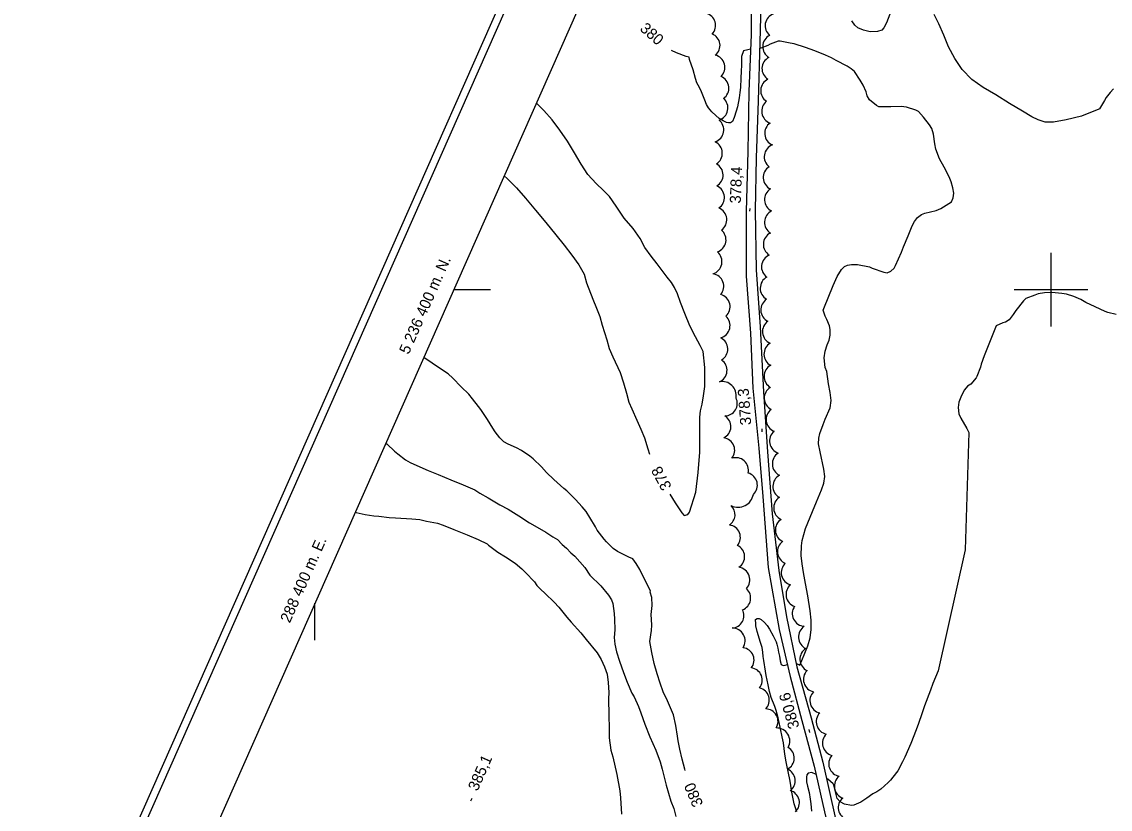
# Model space of a CAD drawing. Extents: x 287698 to 290158, y 5234163 to 5237182.
# Drawn here: x 288320.4 to 288616.1, y 5236258.8 to 5236472.8 of the extents above; entities that cross this region are included whole.
import ezdxf

# ---------------------------------------------------------------- set-up
doc = ezdxf.new("R2010")
doc.units = 0
for name, color, linetype in [('Niveau 1', 7, 'Continuous'), ('Niveau 19', 7, 'Continuous'), ('Niveau 2', 7, 'Continuous'), ('Niveau 3', 7, 'Continuous'), ('Niveau 44', 7, 'Continuous'), ('Niveau 60', 7, 'Continuous'), ('Niveau 61', 7, 'Continuous')]:
    doc.layers.add(name, color=color, linetype=linetype)

msp = doc.modelspace()

# ---------------------------------------------------------------- linework, layer by layer
at = {"layer": 'Niveau 1'}
for points in [[(288540.03, 5236387.65), (288540.05, 5236389.18), (288539.87, 5236390.12), (288539.15, 5236391.91), (288538.65, 5236392.8), (288538.1, 5236394.44), (288538.43, 5236395.32), (288539.48, 5236397.8), (288540.83, 5236401.12), (288541.96, 5236403.55), (288543.09, 5236405.45), (288543.9, 5236406.25), (288544.68, 5236406.67), (288545.84, 5236406.84), (288547.45, 5236406.78), (288550.71, 5236406.15), (288551.43, 5236405.85), (288554.58, 5236404.72), (288555.54, 5236404.55), (288556.47, 5236404.98), (288557.38, 5236405.86), (288557.73, 5236406.58), (288559.39, 5236410.13), (288559.98, 5236411.58), (288561.21, 5236414.61), (288562.31, 5236417.29), (288562.93, 5236418.48), (288563.75, 5236419.56), (288564.8, 5236420.4), (288565.71, 5236420.73), (288568.8, 5236421.49), (288570.09, 5236422.05), (288573, 5236423.83), (288573.44, 5236424.93), (288573.59, 5236426.16), (288573.37, 5236427.65), (288572.93, 5236429.24), (288572.36, 5236430.66), (288570.97, 5236433.29), (288569.76, 5236435.51), (288568.75, 5236438.13), (288568.49, 5236439.61), (288568.07, 5236442.26), (288567.68, 5236443.73), (288567, 5236444.81), (288565.41, 5236446.87), (288564.05, 5236448.38), (288563.27, 5236448.76), (288560.78, 5236449.56), (288559.27, 5236449.73), (288556.5, 5236449.67), (288553.27, 5236449.68), (288552.56, 5236449.98), (288550.72, 5236451.59), (288550.09, 5236452.62), (288549.76, 5236453.72), (288549, 5236455.53), (288548.12, 5236456.91), (288546.64, 5236459.22), (288545.76, 5236459.99), (288544.61, 5236460.69), (288541.62, 5236462.23), (288540.38, 5236462.96), (288538.75, 5236463.67), (288535.82, 5236464.86), (288533.33, 5236465.81), (288530.26, 5236466.78), (288529.17, 5236466.94), (288526.39, 5236467.5), (288525.87, 5236467.49), (288523.72, 5236466.7), (288523.12, 5236466.31), (288521.18, 5236465.57), (288520.88, 5236465.56)], [(288501.66, 5236463.11), (288500.88, 5236463.37), (288498.26, 5236464.34), (288496.92, 5236464.98)], [(288516.45, 5236464.84), (288515.89, 5236463.36), (288515.88, 5236462.83), (288515.92, 5236460.98), (288515.87, 5236459.33), (288515.76, 5236457.45), (288515.64, 5236454.89), (288515.49, 5236453.53), (288515.27, 5236452.14), (288514.84, 5236449.69), (288514.49, 5236448.44), (288513.91, 5236446.72), (288513.44, 5236445.65), (288512.93, 5236445.31), (288512.39, 5236445.29), (288511.85, 5236445.44), (288510.9, 5236445.87), (288509.88, 5236446.5), (288508.99, 5236447.32), (288507.85, 5236448.26), (288506.95, 5236449.36), (288506.42, 5236450.33), (288505.94, 5236451.45), (288505.03, 5236453.71), (288504.47, 5236454.93), (288503.78, 5236456.18), (288503.45, 5236457.37), (288502.76, 5236459.72), (288501.82, 5236462.54), (288501.66, 5236463.11), (288501.66, 5236463.11)], [(288518.36, 5236465.34), (288517.67, 5236465.11), (288516.45, 5236464.84)], [(288617.72, 5236393.25), (288615.44, 5236393.79), (288614.78, 5236394.07), (288611.99, 5236395.31), (288609.47, 5236396.5), (288608.12, 5236397.27), (288606.21, 5236398.09), (288604.21, 5236398.75), (288602.97, 5236398.92), (288600.22, 5236399.18), (288598.29, 5236399.14), (288596.53, 5236398.87), (288595.62, 5236398.51), (288593.21, 5236397.55), (288592.55, 5236396.94), (288590.49, 5236394.33), (288589.78, 5236393.22), (288588.62, 5236391.8), (288587.64, 5236391.11), (288586.95, 5236390.94), (288585.12, 5236390.12), (288584.75, 5236389.24), (288583.27, 5236385.62), (288581.84, 5236382.04), (288581.05, 5236379.78), (288580.88, 5236378.91), (288579.87, 5236376.35), (288579.65, 5236376.06), (288578.21, 5236374.27), (288577.35, 5236373.72), (288576.48, 5236372.78), (288575.71, 5236371.2), (288575.01, 5236369.4), (288574.78, 5236367.99), (288574.98, 5236366.28), (288575.56, 5236365.05), (288577.18, 5236362.27), (288577.7, 5236361.19), (288576.66, 5236329.28)], [(288531.76, 5236297.95), (288532.33, 5236299.21), (288533.97, 5236303.24), (288534.58, 5236305.42), (288534.86, 5236307.65), (288534.85, 5236310.15), (288534.56, 5236312.73), (288533.97, 5236316.75), (288533.3, 5236320.14), (288532.73, 5236323.12), (288532.39, 5236325.51), (288532.16, 5236327.77), (288532.22, 5236330.41), (288532.39, 5236331.85), (288533.32, 5236335.06), (288533.96, 5236336.62), (288535.22, 5236339.71), (288536.28, 5236342.3), (288537.65, 5236345.58), (288538.29, 5236347.37), (288538.56, 5236349.21), (288538.26, 5236351.23), (288537.26, 5236355.96), (288536.88, 5236358.1), (288536.93, 5236359.62), (288537.19, 5236360.86), (288538.08, 5236363.38), (288538.69, 5236364.79), (288539.99, 5236367.88), (288540.31, 5236369.83), (288540.03, 5236372.06), (288539.6, 5236374.44), (288539.08, 5236377.73), (288538.69, 5236378.81), (288538.39, 5236381.44), (288538.67, 5236383.27), (288539.17, 5236384.99), (288539.71, 5236386.3), (288540.03, 5236387.65)], [(288491.2, 5236318.11), (288489.51, 5236321.53), (288488.28, 5236323.99), (288487.33, 5236325.59), (288486.36, 5236326.81), (288485.35, 5236327.32), (288482.21, 5236328.8), (288481.05, 5236329.66), (288479.21, 5236331.47), (288478.64, 5236332.21), (288476.72, 5236334.67), (288476.24, 5236335.51), (288474.73, 5236338.08), (288473.69, 5236339.68), (288472.64, 5236341.02), (288470.82, 5236343.01), (288468.48, 5236345.34), (288467.61, 5236345.99), (288464.9, 5236348.4), (288462.9, 5236350.35), (288461.58, 5236351.81), (288459.34, 5236354.01), (288458.43, 5236354.76), (288456.14, 5236356.28), (288454.82, 5236356.98), (288452.54, 5236357.98), (288451.31, 5236358.67), (288450.27, 5236359.74), (288449.01, 5236361.34), (288448.39, 5236362.33), (288446.89, 5236364.67), (288445.1, 5236367.4), (288444.44, 5236368.24), (288442.86, 5236370.33), (288441.79, 5236371.57), (288439.78, 5236373.61), (288437.52, 5236375.98), (288436.24, 5236377.07), (288434.44, 5236378.32), (288431.86, 5236379.99), (288429.58, 5236381.57)], [(288576.66, 5236329.28), (288569.32, 5236296.38)], [(288500.61, 5236269.3), (288500.49, 5236269.74), (288499.79, 5236272.42), (288499.13, 5236275.09), (288498.67, 5236277.42), (288498.55, 5236278.63), (288498.05, 5236281.55), (288497.41, 5236284.47), (288496.94, 5236285.72), (288495.82, 5236288.26), (288494.67, 5236290.75), (288493.8, 5236293.02), (288492.97, 5236295.61), (288492.17, 5236298.4), (288491.54, 5236301.41), (288491.04, 5236304.43), (288491.5, 5236307.38), (288491.6, 5236308.84), (288491.44, 5236310.4), (288491.42, 5236311.71), (288491.63, 5236314.21), (288491.59, 5236316.31), (288491.1, 5236317.83), (288491.2, 5236318.11)], [(288530.93, 5236258.13), (288530.27, 5236260.25), (288529.95, 5236261.62), (288529.6, 5236263.44), (288529.12, 5236266.42), (288528.61, 5236269.05), (288528.29, 5236270.3), (288528.04, 5236271.73), (288527.74, 5236273.76), (288527.31, 5236276.82), (288527.01, 5236278.52), (288526.52, 5236280.65), (288525.87, 5236283.69), (288525.38, 5236285.65), (288524.95, 5236286.74), (288524.01, 5236289.18), (288523.56, 5236290.82), (288523.17, 5236292.62), (288522.6, 5236295.19), (288522.45, 5236296.32), (288521.99, 5236299.26), (288521.83, 5236300.32), (288521.74, 5236301.47), (288521.53, 5236302.73), (288521.08, 5236304.11), (288520.14, 5236307.09), (288519.86, 5236308.62), (288519.8, 5236309.18), (288519.75, 5236310.35), (288520.19, 5236310.66), (288520.74, 5236310.59), (288521.26, 5236310.33), (288522.2, 5236309.56), (288522.87, 5236308.74), (288523.5, 5236307.72), (288524.56, 5236305.91), (288525.33, 5236304.29), (288525.48, 5236303.67), (288525.83, 5236302.6), (288526, 5236301.52), (288526.26, 5236300.38), (288526.44, 5236299.17), (288526.74, 5236298.16), (288527.21, 5236297.86), (288527.79, 5236297.92), (288528.38, 5236298.15)], [(288530.79, 5236298.37), (288531.47, 5236298.12), (288531.76, 5236297.95)], [(288569.32, 5236296.38), (288567.91, 5236292.95), (288567.27, 5236291.13), (288565.67, 5236286.92), (288564.91, 5236284.73), (288564.05, 5236282.1), (288563.38, 5236280.39), (288561.89, 5236276.67), (288560.3, 5236272.94), (288559.63, 5236271.67), (288558.37, 5236269.21), (288558.01, 5236268.75), (288556.4, 5236266.69), (288555.76, 5236266.08), (288553.78, 5236264.27), (288552.69, 5236263.5), (288551.64, 5236263.03), (288549.98, 5236261.79), (288548.34, 5236260.73), (288546.48, 5236259.89), (288545.79, 5236259.79), (288543.95, 5236260.22), (288542.74, 5236260.78), (288541.91, 5236261.69), (288541.64, 5236262.8), (288541, 5236265.36), (288540.8, 5236265.73), (288539.34, 5236266.94), (288539.07, 5236267.07)], [(288535.03, 5236268.83), (288534.04, 5236268.62), (288533.68, 5236268.16), (288533.56, 5236267.51), (288533.61, 5236266.26), (288533.87, 5236265.07), (288534.3, 5236263.32), (288534.62, 5236261.55), (288534.72, 5236260.25), (288534.91, 5236258.33)], [(288536.18, 5236268.26), (288535.03, 5236268.83)]]:
    msp.add_lwpolyline(points, dxfattribs=at)
at = {"layer": 'Niveau 19'}
for points in [[(288518.52, 5236482.17), (288518.51, 5236469.32), (288517.92, 5236453.86), (288517.66, 5236437.54), (288517.23, 5236421.32), (288517.22, 5236403.64), (288518.39, 5236388.14), (288519.01, 5236373.22), (288520.62, 5236356.96), (288521.68, 5236343.74), (288523.2, 5236324.51), (288526.18, 5236307.64), (288529.13, 5236294.92), (288532.36, 5236282.96), (288535.67, 5236270.53), (288538.48, 5236258.13), (288541.67, 5236245.25), (288545.24, 5236231.69), (288549.17, 5236216.09), (288554.11, 5236200.24), (288558.19, 5236187.81)], [(288521.3, 5236480.92), (288520.93, 5236467.19), (288520.46, 5236451.28), (288519.89, 5236435.79), (288519.6, 5236421.45), (288519.87, 5236405.37), (288520.97, 5236389.91), (288521.87, 5236372.23), (288522.99, 5236355.92), (288524.29, 5236339.04), (288526.08, 5236323.71), (288528.12, 5236311.11), (288530.98, 5236297.47), (288534.85, 5236283.63), (288538.06, 5236271.56), (288541.5, 5236256.24), (288545.27, 5236242), (288548.74, 5236229.5), (288552.67, 5236214.05), (288558.01, 5236199.12), (288561.49, 5236186.39)]]:
    msp.add_lwpolyline(points, dxfattribs=at)
at = {"layer": 'Niveau 2'}
for points in [[(288556.72, 5236476.04), (288555.35, 5236472.44), (288554.6, 5236471.1), (288554.05, 5236470.53), (288552.84, 5236470.16), (288550.88, 5236470.07), (288549.03, 5236470.48), (288547.57, 5236471.14), (288546.71, 5236471.87), (288545.87, 5236473.02)], [(288617, 5236454.52), (288616.06, 5236453.56), (288614.99, 5236452.2), (288614.55, 5236451.36), (288613.2, 5236449.15), (288612.99, 5236449.04), (288608.29, 5236447.16), (288604.14, 5236446.11), (288600.68, 5236445.53), (288598.44, 5236445.46), (288596.57, 5236446.16), (288594.8, 5236446.98), (288592.24, 5236448.48), (288588.73, 5236450.61), (288584.99, 5236452.91), (288581.61, 5236454.93), (288578.48, 5236457.11), (288575.89, 5236459.8), (288573.85, 5236462.79), (288572.2, 5236465.96), (288570.86, 5236469.13), (288569.55, 5236472.17), (288568.31, 5236474.76)], [(288503.5, 5236344.96), (288504.19, 5236350.28), (288504.62, 5236355.8), (288504.63, 5236365.3), (288504.79, 5236367.03), (288505.26, 5236368.89), (288505.61, 5236371.14), (288505.92, 5236373.71), (288505.98, 5236376.27), (288505.94, 5236378.83), (288505.49, 5236383.2), (288504.66, 5236384.79), (288503.43, 5236387.19), (288501.89, 5236390.15), (288500.52, 5236393.53), (288499.39, 5236396.49), (288498.54, 5236398.89), (288497.74, 5236400.53), (288496.9, 5236401.9), (288495.76, 5236403.35), (288492.99, 5236406.99), (288491.34, 5236409.05), (288489.64, 5236411.4), (288488.37, 5236413.93), (288486.48, 5236416.6), (288484, 5236419.44), (288481.9, 5236422.63), (288480.07, 5236425.28), (288478.39, 5236426.96), (288476.41, 5236428.79), (288474.19, 5236431.25), (288472.33, 5236434.08), (288470.55, 5236437.15), (288468.6, 5236440.31), (288466.54, 5236443.33), (288464.5, 5236446.09), (288462.22, 5236448.66), (288460.18, 5236450.7)], [(288451.44, 5236430.95), (288452.22, 5236430.23), (288454.74, 5236427.63), (288457.19, 5236424.87), (288459.93, 5236421.6), (288462.79, 5236418.25), (288465.44, 5236414.89), (288467.72, 5236412.08), (288469.85, 5236409.38), (288471.71, 5236406.72), (288473.13, 5236404.16), (288473.78, 5236401.84), (288475.51, 5236397.36), (288476.53, 5236394.95), (288477.39, 5236392.65), (288478.06, 5236390.33), (288479.37, 5236386.36), (288480, 5236383.99), (288480.98, 5236381.76), (288482.93, 5236377.48), (288483.84, 5236374.67), (288484.63, 5236371.85), (288485.35, 5236369.44), (288486.15, 5236367.58), (288487.46, 5236364.51), (288488.54, 5236362.05), (288489.54, 5236359.72), (288490.51, 5236356.7), (288490.9, 5236355.3)], [(288419.28, 5236358.32), (288419.61, 5236358.03), (288421.62, 5236356.12)], [(288421.62, 5236356.12), (288422.53, 5236355.39), (288424.63, 5236353.79), (288425.92, 5236353.02), (288427.72, 5236352.18), (288430.76, 5236350.85), (288433.47, 5236349.73), (288436.91, 5236348.33), (288440.28, 5236346.95), (288443.42, 5236345.57), (288444.86, 5236344.69), (288447.1, 5236343.42), (288450.24, 5236341.56), (288452.56, 5236340.33), (288455.41, 5236338.55), (288458.35, 5236336.64), (288460.38, 5236335.42), (288462.79, 5236334.09)], [(288496.49, 5236344.44), (288497.16, 5236343.21), (288497.9, 5236342.02), (288499.72, 5236339.35), (288500.31, 5236338.62), (288501.34, 5236338.85), (288501.77, 5236339.51), (288503.5, 5236344.96)], [(288410.95, 5236339.5), (288411.18, 5236339.47), (288413.68, 5236338.93), (288416.05, 5236338.53), (288417.36, 5236338.45), (288420.17, 5236338.1), (288421.95, 5236338.02), (288426.38, 5236337.71), (288428.54, 5236337.5), (288430.33, 5236337.12), (288433.33, 5236336.53), (288434.87, 5236335.99), (288437.79, 5236334.84), (288441.36, 5236333.38), (288444.36, 5236332.12), (288446.8, 5236330.93), (288447.17, 5236330.52), (288449.69, 5236328.62), (288451.8, 5236327.35), (288454.4, 5236325.64), (288456.21, 5236324.13), (288457.26, 5236323.09), (288459.66, 5236320.58), (288460.32, 5236319.6), (288461.3, 5236318.56), (288462.58, 5236317.46), (288465.06, 5236315.07), (288466.25, 5236313.68), (288468.44, 5236310.96), (288469.63, 5236309.63), (288472.27, 5236306.7), (288473.7, 5236304.96), (288476.67, 5236301.35), (288477.83, 5236299.46), (288478.71, 5236297.54), (288479.38, 5236295.5), (288479.69, 5236293.22), (288479.84, 5236290.54), (288479.77, 5236288.77), (288479.85, 5236284.35), (288479.92, 5236280.77), (288479.99, 5236278.22), (288480.43, 5236274.89), (288480.93, 5236273.06), (288482.02, 5236268.29), (288482.85, 5236263.82), (288483.03, 5236261.92), (288483.34, 5236257.49)], [(288462.79, 5236334.09), (288463.83, 5236333.34), (288464.63, 5236332.84), (288465.95, 5236332.07), (288467.16, 5236330.78), (288468.37, 5236329.76), (288469.57, 5236328.47), (288470.64, 5236327.57), (288471.98, 5236326.02), (288473.32, 5236324.48), (288474.67, 5236322.41), (288477.7, 5236319.5), (288479.75, 5236317), (288480.57, 5236315.71), (288480.93, 5236314.72), (288481.35, 5236311.99), (288481.44, 5236310.48), (288481.52, 5236307.53), (288481.3, 5236305.51), (288481.51, 5236303.69), (288481.99, 5236301.57), (288482.78, 5236299.04), (288483.9, 5236295.99), (288484.86, 5236293.32), (288486.12, 5236290.38), (288486.79, 5236289.33), (288487.97, 5236286.73), (288488.54, 5236285.03), (288489.66, 5236281.88), (288491.04, 5236278.44), (288492.6, 5236274.82), (288493.85, 5236271.68), (288494.37, 5236269.67), (288495.45, 5236265.36), (288496.75, 5236260.98), (288497.51, 5236259.04), (288498.12, 5236256.83)]]:
    msp.add_lwpolyline(points, dxfattribs=at)
at = {"layer": 'Niveau 3'}
for p, q in [((288518.22, 5236421.28), (288518.24, 5236422.08)), ((288521.58, 5236361.37), (288521.52, 5236362.16)), ((288534.51, 5236279.68), (288534.31, 5236280.45)), ((288442.42, 5236261.12), (288442.74, 5236261.85))]:
    msp.add_line(p, q, dxfattribs=at)
at = {"layer": 'Niveau 44'}
for centre, radius, start, end in [((288507.96, 5236460.37), 3.44, 314.2525, 76.0403), ((288525.29, 5236412.28), 3.43, 116.2563, 238.0093), ((288509.35, 5236390.23), 3.46, 285.8821, 47.5174), ((288525.48, 5236376.41), 3.43, 118.1646, 239.9225), ((288525.54, 5236370.51), 3.43, 121.3653, 243.4145), ((288511.36, 5236369.1), 3.41, 271.2027, 25.7634), ((288509.63, 5236362.79), 3.41, 295.9778, 58.0653), ((288526.98, 5236358.85), 3.43, 129.6834, 251.8138), ((288510.67, 5236356.34), 3.41, 320.2446, 82.3321), ((288514.4, 5236350.93), 3.41, 346.8638, 108.9513), ((288516.83, 5236346.86), 3.41, 312.6746, 74.762), ((288510.78, 5236338.86), 3.39, 303.6279, 46.3798), ((288512.21, 5236332.66), 3.41, 320.3657, 82.4532), ((288513.4, 5236327.42), 3.38, 302.6222, 64.7481), ((288536.2, 5236294.1), 3.44, 136.1414, 257.896), ((288525.51, 5236277.34), 3.55, 330.8171, 92.7243)]:
    msp.add_arc(centre, radius, start, end, dxfattribs=at)
for centre, major_axis, ratio, start_param, end_param in [((288505.46, 5236471.77), (3.29, 1.01), 0.98251, 5.224913, 7.316794), ((288525.79, 5236471.67), (-3.39, 0.68), 0.987711, 5.242899, 7.348291), ((288506.71, 5236466.34), (3.35, 0.45), 0.987661, 5.242378, 7.350604), ((288525.12, 5236466.02), (-3.43, 0.11), 0.997996, 5.216118, 7.342483), ((288524.94, 5236460.05), (-3.45, 0.12), 0.987386, 5.225791, 7.333127), ((288509.05, 5236454.74), (3.41, 0.39), 0.99995, 5.220723, 7.349224), ((288524.58, 5236454.05), (-3.43, 0.24), 0.999861, 5.22158, 7.346593), ((288508.8, 5236449.36), (3.36, -0.71), 0.999644, 5.222398, 7.347905), ((288524.85, 5236448.49), (-3.42, -0.34), 0.999127, 5.287263, 7.410111), ((288507.65, 5236443.4), (3.4, -0.58), 0.999205, 5.220459, 7.341122), ((288525.66, 5236442.46), (-3.42, -0.02), 0.999593, 5.318082, 7.444553), ((288507.29, 5236437.07), (-3.06, 1.54), 0.999983, 2.591512, 4.72158), ((288525.53, 5236436.1), (1.29, -3.18), 0.999995, 3.118916, 5.244393), ((288507.5, 5236431.12), (3.41, -0.37), 0.999761, 5.352125, 7.47881), ((288525.27, 5236430.45), (-3.44, 0.19), 0.999687, 5.328788, 7.459649), ((288507.85, 5236425.01), (3.44, 0.05), 0.999386, 5.301407, 7.423698), ((288525.6, 5236424.44), (3.07, -1.53), 0.999983, 2.594542, 4.719724), ((288508.46, 5236418.99), (3.45, 0.39), 0.998427, 5.213855, 7.343238), ((288525.61, 5236418.27), (-3.42, 0.41), 0.999132, 5.288768, 7.409295), ((288508.28, 5236413.51), (3.38, -0.6), 0.998751, 5.218793, 7.342389), ((288507.12, 5236407.61), (3.23, -1.31), 0.999887, 5.406739, 7.532437), ((288524.79, 5236406.2), (1.41, -3.13), 0.999995, 3.114167, 5.245211), ((288507.67, 5236400.89), (3.21, 1.23), 0.999446, 5.216436, 7.341908), ((288524.45, 5236400.38), (-3.44, 0.03), 0.999994, 5.217083, 7.34627), ((288509.36, 5236395.34), (3.37, 0.79), 0.999951, 5.221375, 7.349855), ((288524.58, 5236394.49), (-3.42, -0.2), 0.999911, 5.219839, 7.342951), ((288525.05, 5236388.6), (-3.43, -0.15), 0.999131, 5.282228, 7.412384), ((288508.74, 5236383.83), (3.44, 0.12), 0.999994, 5.222758, 7.348898), ((288525.46, 5236382.47), (-3.28, 1.02), 0.999961, 5.543954, 7.673211), ((288508.57, 5236378.06), (3.41, -0.34), 0.999645, 5.217033, 7.347218), ((288510.73, 5236371.24), (-3.58, 1.16), 0.999995, 3.278897, 5.244752), ((288526.06, 5236364.69), (2.11, -2.72), 0.999995, 3.119179, 5.24327), ((288527.74, 5236352.67), (-3.44, -0.19), 0.999994, 5.215976, 7.347362), ((288527.89, 5236346.55), (-3.42, 0.37), 0.999596, 5.320205, 7.448757), ((288515, 5236345.07), (1.09, -4.06), 0.999509, 5.561134, 7.418464), ((288528.1, 5236340.7), (-3.43, 0.12), 0.999684, 5.333104, 7.462403), ((288528.55, 5236334.69), (-3.43, 0.06), 0.999496, 5.308613, 7.43773), ((288529.13, 5236328.8), (-3.42, -0.41), 0.999329, 5.222667, 7.34529), ((288530.17, 5236323.11), (-3.37, -0.74), 0.99581, 5.246527, 7.367323), ((288514.62, 5236321.08), (-2.71, 2.29), 0.999995, 3.117912, 5.244), ((288531.44, 5236317.18), (-3.37, -0.65), 0.996218, 5.220186, 7.338209), ((288515.1, 5236316.2), (-0.21, 3.36), 0.983728, 3.416625, 5.502204), ((288533.17, 5236311.97), (-3.24, -1.2), 0.999599, 5.319055, 7.4463), ((288513.27, 5236311.4), (2.01, 2.69), 0.981472, 3.838846, 5.85176), ((288513.4, 5236304.55), (3.09, 1.68), 0.999868, 5.2218, 7.346986), ((288534.9, 5236305.62), (-3.49, -0.18), 0.994627, 5.240449, 7.357852), ((288515.95, 5236299.33), (3.13, 1.3), 0.995497, 5.214798, 7.332119), ((288535.24, 5236299.57), (-3.44, -0.18), 0.999911, 5.224439, 7.346313), ((288518.19, 5236293.87), (3.13, 1.29), 0.99835, 5.216436, 7.343894), ((288520.08, 5236288.45), (3.31, 0.74), 0.999109, 5.285148, 7.412993), ((288537.92, 5236288.32), (-3.42, 0.15), 0.999961, 5.546976, 7.676881), ((288522.47, 5236282.69), (2.96, 1.64), 0.998713, 5.21793, 7.341743), ((288539.66, 5236282.61), (-3.28, -1.03), 0.999994, 5.218295, 7.34317), ((288541.34, 5236276.76), (-3.36, -0.73), 0.997886, 5.261379, 7.385218), ((288526.87, 5236272.71), (3.17, -1.19), 0.99996, 5.544383, 7.672868), ((288543.04, 5236271.17), (-3.31, -0.89), 0.999384, 5.297241, 7.427361), ((288527.15, 5236266.56), (3.38, -0.09), 0.999823, 5.377238, 7.499861), ((288544.61, 5236265.08), (-3.41, -0.56), 0.996561, 5.213009, 7.338863), ((288528.29, 5236260.59), (3.36, -0.3), 0.99996, 5.549195, 7.677495), ((288545.63, 5236259.24), (-3.36, -0.66), 0.998567, 5.219281, 7.345445)]:
    msp.add_ellipse(centre, major_axis=major_axis, ratio=ratio, start_param=start_param, end_param=end_param, dxfattribs=at)
at = {"layer": 'Niveau 60'}
for points in [[(289088.15, 5234163.34), (287698.12, 5234778.71), (288762.01, 5237181.96), (290152.07, 5236566.6), (289088.15, 5234163.34)], [(289087.13, 5234165.98), (287700.76, 5234779.73), (288763.06, 5237179.33), (290149.43, 5236565.58), (289087.13, 5234165.98)]]:
    msp.add_lwpolyline(points, dxfattribs=at)
msp.add_lwpolyline([(289077.96, 5234189.73), (287724.51, 5234788.9), (288562.53, 5236681.9), (289915.99, 5236082.74)], close=True, dxfattribs=at)
at = {"layer": 'Niveau 61'}
for p, q in [((288437.73, 5236400), (288447.73, 5236400)), ((288400, 5236304.76), (288400, 5236314.76))]:
    msp.add_line(p, q, dxfattribs=at)
for points in [[(288600, 5236410), (288600, 5236400), (288600, 5236390)], [(288590, 5236400), (288600, 5236400), (288610, 5236400)]]:
    msp.add_lwpolyline(points, dxfattribs=at)

# ---------------------------------------------------------------- texts
at = {"layer": 'Niveau 1'}
for rotation, p in [(318.5843, (288488.1, 5236470.6)), (112.9623, (288505.58, 5236260.19))]:
    msp.add_text('380', height=3, rotation=rotation, dxfattribs=at).set_placement(p)
at = {"layer": 'Niveau 2'}
msp.add_text('378', height=3, rotation=118.3834, dxfattribs=at).set_placement((288497.05, 5236346.45))
at = {"layer": 'Niveau 3'}
for s, rotation, p in [('378,4', 87.6703, (288515.71, 5236423.34)), ('378,3', 94.2101, (288518.59, 5236363.27)), ('380,6', 105.9686, (288531.7, 5236281.15)), ('385,1', 66.1217, (288444.2, 5236263.55))]:
    msp.add_text(s, height=3, rotation=rotation, dxfattribs=at).set_placement(p)
at = {"layer": 'Niveau 61'}
for s, p in [('5 236 400 m. N.', (288425.49, 5236382.22)), ('288 400 m. E.', (288393.18, 5236309.23))]:
    msp.add_text(s, height=3, rotation=66.1213, dxfattribs=at).set_placement(p)

doc.saveas('drawing.dxf')
